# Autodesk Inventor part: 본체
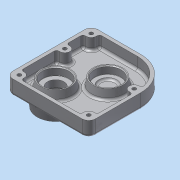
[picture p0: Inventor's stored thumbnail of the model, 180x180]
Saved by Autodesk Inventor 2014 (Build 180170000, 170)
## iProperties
Created: 2015-11
Part Number: 본체
Material: 알루미늄 6061
Document SubType Name: Modeling
Designer: dgall
Density: 2.71 g/cm^3
Appearance: 알루미늄 - 평지
Author: dgall
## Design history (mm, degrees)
sketch "스케치1"
  geometry: L1 (-50, 51.5)-(-50, -51.5); L2 (-50, -51.5)-(50, -51.5); L3 (50, -51.5)-(50, 11.5); L4 (10, 51.5)-(-50, 51.5); A1 r 40 centre (10, 11.5) between (50, 11.5) and (10, 51.5); 3 further points
  constraints: 8 end point, 2 midpoint, 2 parallel, 2 point on circle, 2 tangent, 1 centre point, 1 horizontal alignment, 1 perpendicular, 1 vertical, 1 vertical alignment
  dimensions: "d0" = 100 distance of L1.end L2.end; "d1" = 103 distance of L1.start L1.end; "d2" = 40 radius of A1
extrude "돌출1" new body sketch "스케치1" distance "d3" = 18; taper "d4" = 0 deg
node "작업 평면2"
sketch "스케치3"
  geometry: L1 (-50, 51.5)-(-50, -51.5) reference; L2 (10, 51.5)-(-50, 51.5) reference; L3 (50, -51.5)-(50, 11.5) reference; L4 (-50, -51.5)-(50, -51.5) reference; L5 (10, 47.5)-(-46, 47.5); L6 (-46, 47.5)-(-46, -47.5); L7 (-46, -47.5)-(46, -47.5); L8 (46, -47.5)-(46, 11.5); A1 r 40 centre (10, 11.5) between (50, 11.5) and (10, 51.5) reference; A2 r 36 centre (10, 11.5) between (46, 11.5) and (10, 47.5); 1 further point
  constraints: 8 end point, 2 point on circle, 1 centre point, 4 other
  dimensions: "d15" = 4 distance between parallel lines of L5 L2
extrude "돌출2" cut sketch "스케치3" distance "d16" = 18; taper "d17" = 0 deg
sketch "스케치4"
  geometry: L1 (-50, 51.5)-(-50, -51.5) reference; L2 (-50, -51.5)-(50, -51.5) reference; L3 (50, -51.5)-(50, 11.5) reference; L4 (10, 51.5)-(-50, 51.5) reference; C1 r 6 at (-42, 43.5); C2 r 6 at (-42, -43.5); C3 r 6 at (42, -43.5); C4 r 6 at (42, 11.5); C5 r 6 at (-42, 11.5); 1 further point
  constraints: 5 centre point, 4 equal radius, 3 vertical alignment, 2 horizontal alignment
  dimensions: "d18" = 8 distance from line of C1.centre L1; "d19" = 8 distance from line of L3 C3.centre; "d20" = 8 distance from line of C3.centre L2; "d21" = 12 diameter of C2; "d22" = 8 distance from line of C1.centre L4; "d23" = 55 distance of C4.centre C3.centre
extrude "돌출3" join sketch "스케치4" distance "d24" = 18; taper "d25" = 0 deg
sketch "스케치5"
  geometry: L1 (-50, 51.5)-(-50, -51.5) reference; L2 (-50, -51.5)-(50, -51.5) reference; C1 r 20 at (10, 11.5); 1 further point
  constraints: 1 centre point
  dimensions: "d26" = 60 distance from line of C1.centre L1; "d27" = 63 distance from line of L2 C1.centre; "d28" = 40 diameter of C1
extrude "돌출4" join sketch "스케치5" distance "d29" = 11; taper "d30" = -10 deg
sketch "스케치6"
  geometry: C1 r 18.06 at (0, 0) reference; C2 r 16 at (0, 0); C3 r 11 at (0, 0); 1 further point
  constraints: 2 centre point, 2 coincident
  dimensions: "d31" = 32 diameter of C2; "d32" = 22 diameter of C3
extrude "돌출5" cut sketch "스케치6" distance "d33" = 9; taper "d34" = 0 deg
extrude "돌출6" cut sketch "스케치6" distance "d35" = 11; taper "d36" = 0 deg
sketch "스케치7"
  geometry: L1 (-50, -51.5)-(50, -51.5) reference; L2 (-50, 51.5)-(-50, -51.5) reference; C1 r 20 at (-20, -21.5); 1 further point
  constraints: 1 centre point
  dimensions: "d37" = 30 distance from line of L1 C1.centre; "d38" = 30 distance from line of C1.centre L2; "d39" = 40 diameter of C1
extrude "돌출7" join sketch "스케치7" distance "d40" = 11; taper "d41" = -10 deg
sketch "스케치8"
  geometry: L1 (50, 51.5)-(50, -51.5) reference; L2 (50, -51.5)-(-50, -51.5) reference; C1 r 25 at (20, -21.5); 1 further point
  constraints: 1 centre point
  dimensions: "d52" = 50 diameter of C1; "d53" = 30 distance from line of L1 C1.centre; "d54" = 30 distance from line of C1.centre L2
extrude "돌출8" join sketch "스케치8" distance "d42" = 15; taper "d43" = -10 deg
node "작업 평면3"
sketch "스케치9"
  geometry: L1 (15, 48.06)-(15, 11.94) reference; L2 (-15, 30)-(15, 30); L3 (-15, 44)-(-4, 44); L4 (-4, 44)-(-4, 42); L5 (-4, 42)-(-2, 42); L6 (-2, 42)-(-2, 40); L7 (-2, 40)-(6, 40); L8 (6, 40)-(6, 46); L9 (6, 46)-(15, 46); L10 (-15, 7.645)-(-15, 52.355) reference; L11 (-15, 44)-(-15, 30); L12 (15, 46)-(15, 30); 2 further points
  constraints: 20 end point, 7 parallel, 2 midpoint, 2 perpendicular, 1 point on line, 1 vertical alignment
  dimensions: "d45" = 32 diameter of L9 L2; "d46" = 20 diameter of L7 L2; "d47" = 24 diameter of L5 L2; "d50" = 2 distance between parallel lines of L6 L4; "d51" = 9 distance between parallel lines of L1 L8; "d55" = 28 diameter of L3 L2; "d56" = 11 distance between parallel lines of L4 L10
revolve "회전1" sketch "스케치9" stored, may be unused: angle "d57" = 90 deg
hole "구멍1" diameter "d60" = 4.5; stored, may be unused: countersink angle "d64" = 90 deg, drill point angle "d66" = 118 deg; dims "d58" = 10, "d59" = 10, "d61" = 6, "d62" = 8, "d63" = 4.4, "d65" = 8
hole "구멍2" diameter "d69" = 4.5; stored, may be unused: countersink angle "d73" = 90 deg, drill point angle "d75" = 118 deg; dims "d67" = 10, "d68" = 10, "d70" = 6, "d71" = 8, "d72" = 4.4, "d74" = 8
hole "구멍3" diameter "d78" = 4.5; stored, may be unused: countersink angle "d82" = 90 deg, drill point angle "d84" = 118 deg; dims "d76" = 10, "d77" = 10, "d79" = 6, "d80" = 8, "d81" = 4.4, "d83" = 8
hole "구멍4" diameter "d87" = 4.5; stored, may be unused: countersink angle "d91" = 90 deg, drill point angle "d93" = 118 deg; dims "d85" = 10, "d86" = 10, "d88" = 6, "d89" = 8, "d90" = 4.4, "d92" = 8
hole "구멍5" diameter "d96" = 4.5; stored, may be unused: countersink angle "d100" = 90 deg, drill point angle "d102" = 118 deg; dims "d94" = 10, "d95" = 10, "d97" = 6, "d98" = 8, "d99" = 4.4, "d101" = 8
sketch "스케치10"
  geometry: C1 r 14 at (0, 0) reference; 2 further points
  constraints: 1 vertical alignment
  dimensions: "d103" = 18 distance of C1.centre point (0, 18)
hole "구멍6" sketch "스케치10" at (0, 18) diameter "d104" = 2.459; stored, may be unused: countersink angle "d108" = 90 deg, drill point angle "d110" = 118 deg; dims "d105" = 8, "d106" = 8, "d107" = 4.4, "d109" = 10
sketch "스케치11"
  geometry: L1 (50, 51.5)-(50, -51.5) reference; L2 (-10, 51.5)-(50, 51.5) reference; 2 further points
  constraints: 1 other
  dimensions: "d114" = 40 distance from line of L1 point (10, 31.5); "d115" = 20 distance from line of point (10, 31.5) L2
feature "엠보싱1" sketch "스케치11" dims "d15" = 4, "d116" = 0.5, "d117" = 0
fillet "모깎기1" dims "d118" = 8
fillet "모깎기4" dims "d121" = 0.3
fillet "모깎기5" dims "d122" = 3
fillet "모깎기6" dims "d123" = 3
fillet "모깎기7" dims "d124" = 3
fillet "모깎기8" dims "d125" = 3
fillet "모깎기9" dims "d126" = 3
chamfer "모따기1" distance "d127" = 1; stored, may be unused: second distance "d128" = 2, angle "d129" = 45 deg
fillet "모깎기10" dims "d130" = 3
fillet "모깎기11" dims "d131" = 3
fillet "모깎기12" dims "d132" = 0.3
node "솔리드1"
pattern_circular "원형 패턴1" dims angle "d112" = 360 deg
node "투영된 루프1"
other parameters: "d14" = -14
